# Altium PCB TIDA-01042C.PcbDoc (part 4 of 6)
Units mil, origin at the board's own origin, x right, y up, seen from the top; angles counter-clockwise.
Board outline 8300 x 7100 mil, 8 copper layers (Top Layer, Signal Layer 1, Signal Layer 2, Signal Layer 3, Signal Layer 4, Signal Layer 5, Signal Layer 6, Bottom Layer), stack 59.2 mil thick; 551 components, 303 nets, 1611 pads, 2322 vias.
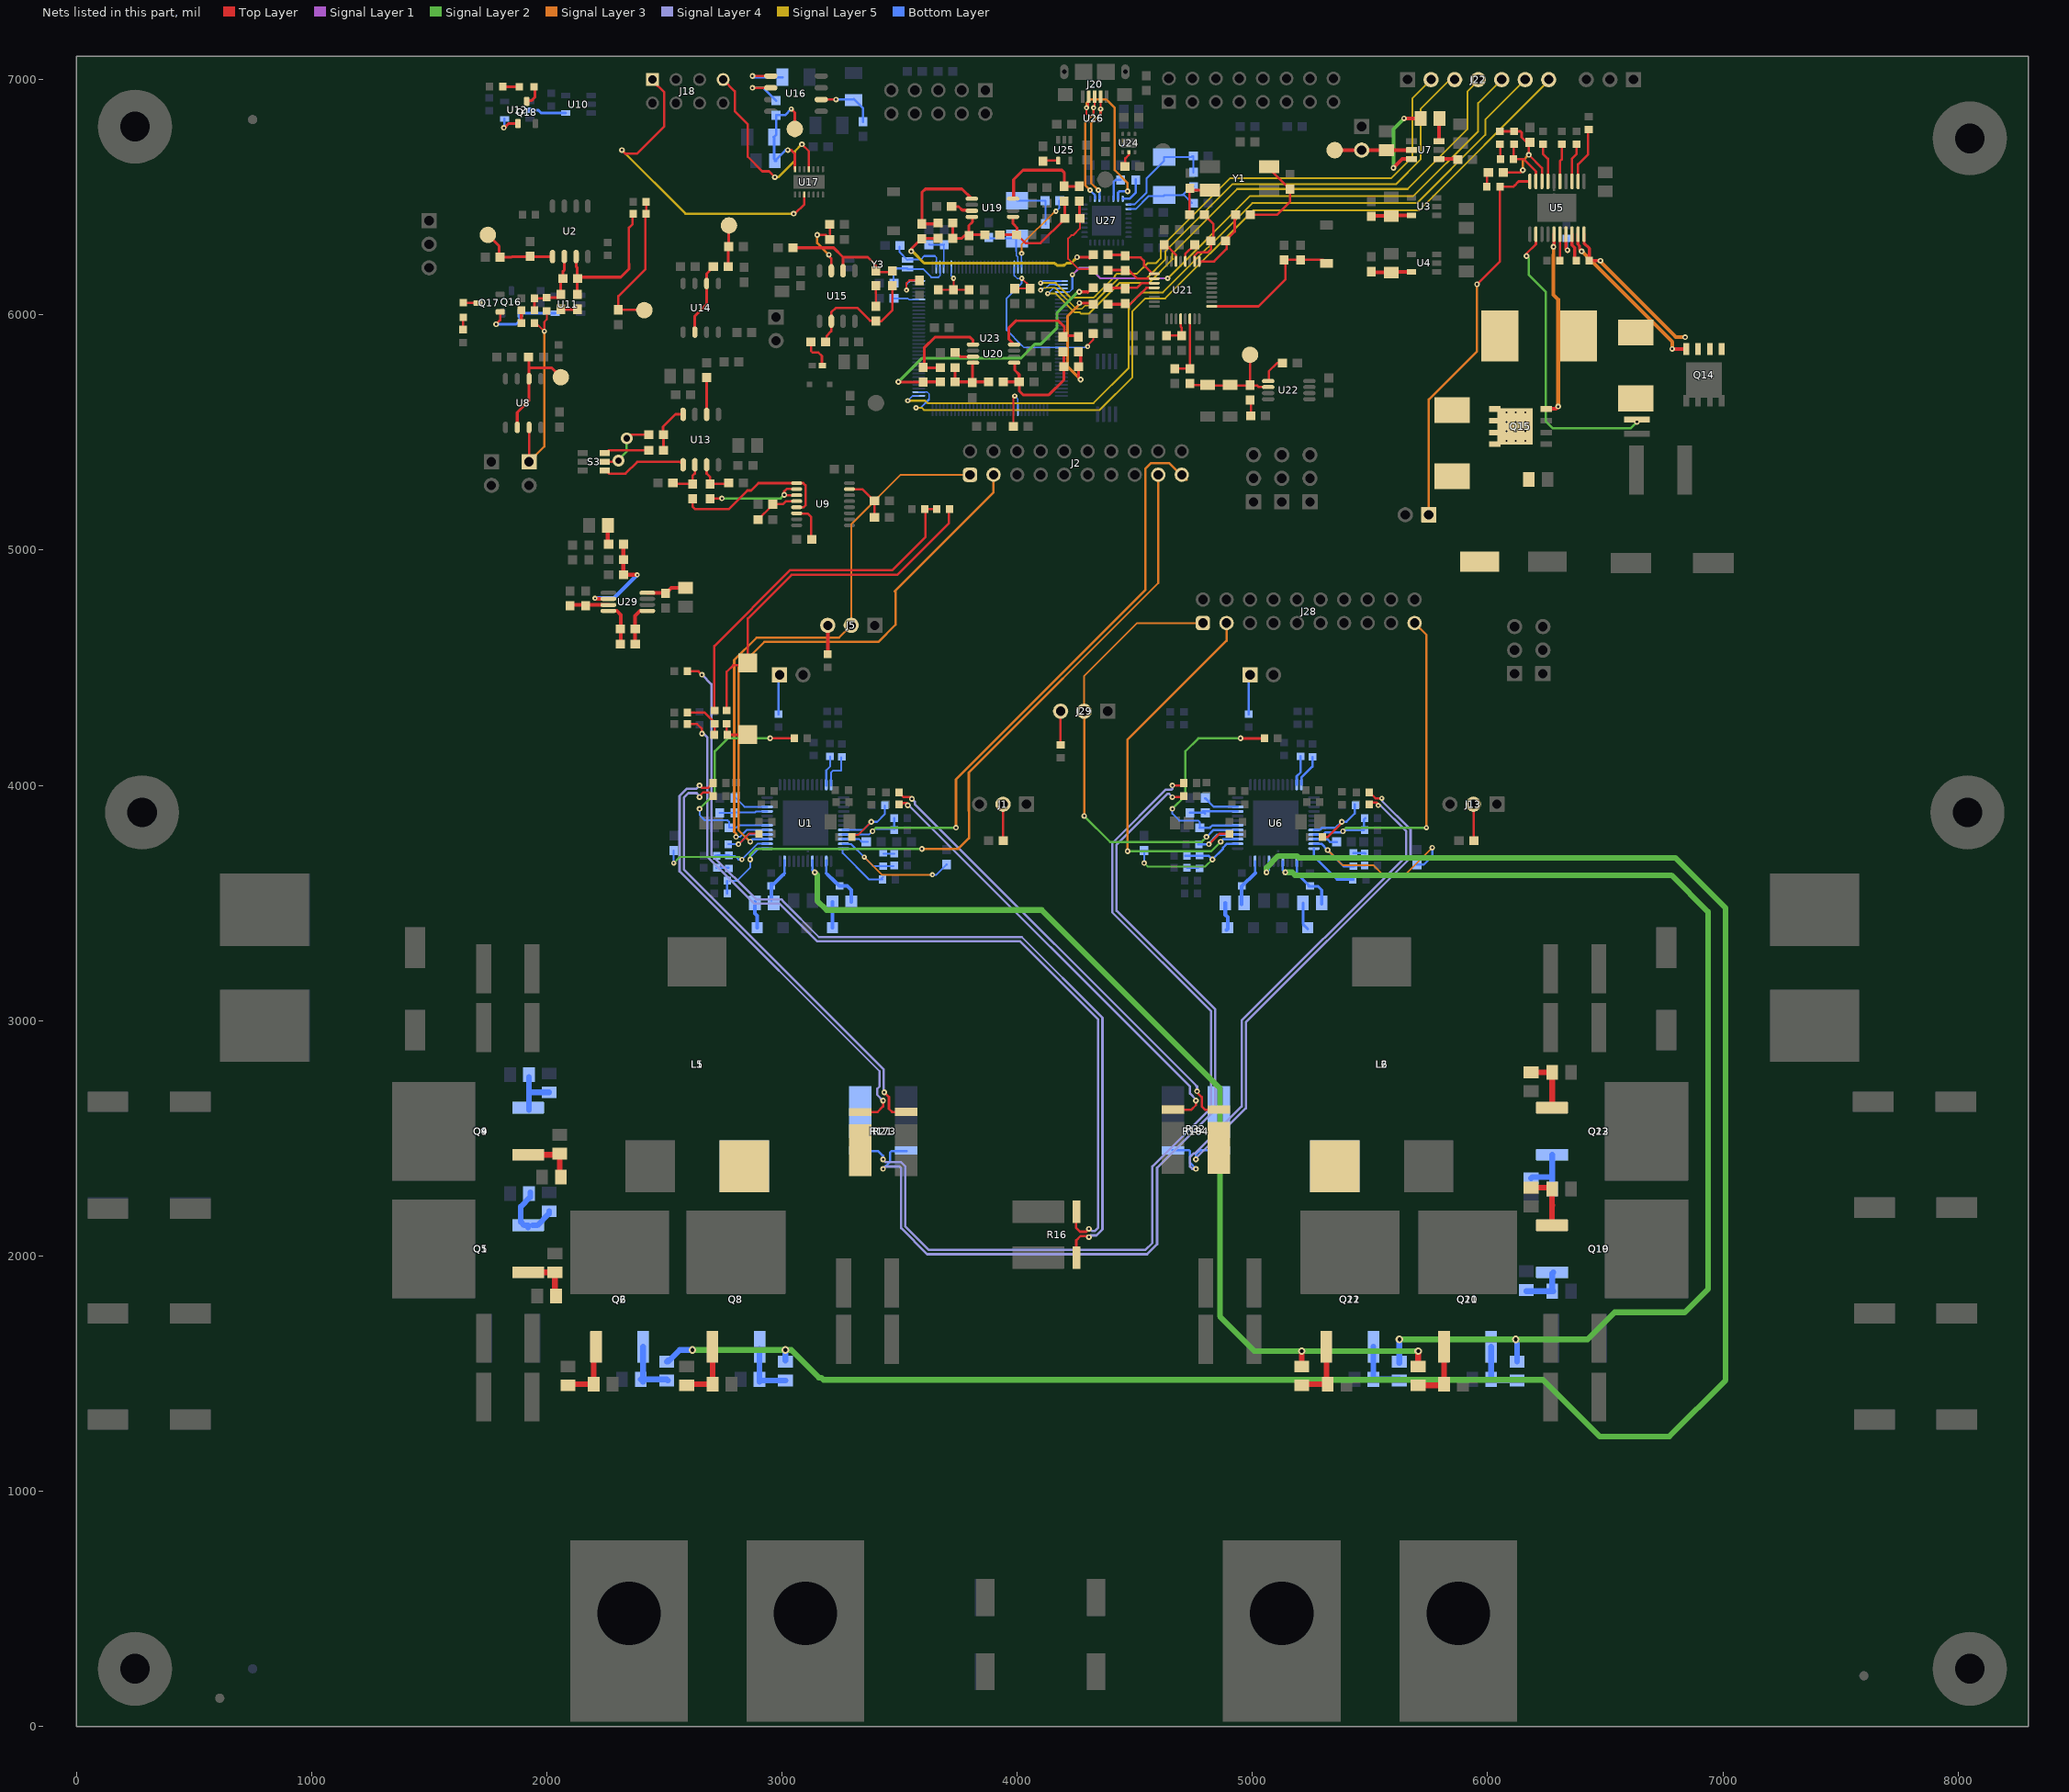
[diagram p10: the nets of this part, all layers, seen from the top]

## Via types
v1: diameter 32, hole 16, Top Layer to Bottom Layer, tented both sides, 1077 vias
v2: diameter 22, hole 8, Top Layer to Bottom Layer, tented both sides, 583 vias
v3: diameter 32, hole 16, Top Layer to Bottom Layer, 233 vias
v4: diameter 24, hole 10, Top Layer to Bottom Layer, tented both sides, 153 vias
v5: diameter 24, hole 8, Top Layer to Bottom Layer, 96 vias
v6: diameter 19.68, hole 7.87, Top Layer to Bottom Layer, 70 vias
v7: diameter 24, hole 10, Top Layer to Bottom Layer, 44 vias
v8: diameter 28, hole 8, Top Layer to Bottom Layer, tented top, 24 vias
v9: diameter 22, hole 8, Top Layer to Bottom Layer, 18 vias
v10: diameter 19.68, hole 8, Top Layer to Bottom Layer, 16 vias
v11: diameter 50, hole 28, Top Layer to Bottom Layer, 3 vias
v12: diameter 36, hole 20, Top Layer to Bottom Layer, 2 vias
v13: diameter 26, hole 12, Top Layer to Bottom Layer, 1 vias
v14: diameter 28, hole 12, Top Layer to Bottom Layer, tented both sides, 1 vias
v15: diameter 24, hole 10, Top Layer to Bottom Layer, tented top, 1 vias

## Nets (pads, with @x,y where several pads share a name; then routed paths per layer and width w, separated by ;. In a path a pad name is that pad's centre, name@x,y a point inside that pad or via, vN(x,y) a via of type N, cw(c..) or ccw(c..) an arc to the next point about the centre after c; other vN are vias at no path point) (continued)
LO2: R38.1 R39.1 U1.17 | length 4223.8
  Top Layer w24: R39.1@5210,1530 v1(5210,1595) ; R38.1@5705,1530 v1(5705,1595)
  Signal Layer 2 w24: v4@3141.87,3628.13 3150,3620 3150,3510 3190,3470 4105,3470 4861.87,2713.13 4861.87,1743.13 5010,1595 v1(5210,1595) v1(5705,1595)
  Bottom Layer w9.8: 3129.53,3640.47 U1.17@3129.53,3681.54
  Bottom Layer w12: 3129.53,3640.47 v4(3140,3630)
LO3: R180.1 R181.1 U6.20 | length 8995.4
  Signal Layer 2 w24: v1(2620,1600) v1(3015,1600) 3040,1600 3157.54,1482.46 3167.46,1482.46 3176.8,1473.13 6235.92,1473.13 ; v4(5060,3630) 5060,3650 5110,3700 5190.08,3700 5198.2,3691.87 6798.2,3691.87 6800.08,3690 6800.15,3690 7011.87,3478.28 7011.87,1471.8 6772.33,1232.25 6476.8,1232.25 6235.92,1473.13 ; 6254.52,1454.52 6235.92,1473.13
  Bottom Layer w9.8: v4(5060,3630) 5070.47,3640.47 U6.20@5070.47,3677.6
  Bottom Layer w24: R180.1@2515,1555 R180.1@2510,1550 2515,1550 2565,1600 v1(2620,1600) ; R181.1@3015,1555 v1(3015,1600)
LO4: R191.1 R192.1 U6.17 | length 5117.7
  Signal Layer 2 w24: v4(5140,3630) 5169.92,3630 5181.8,3618.13 6781.87,3618.13 6936.84,3463.16 6936.84,1858.63 6838.2,1760 6540,1760 6425,1645 v1(6120,1645) v1(5625,1645)
  Bottom Layer w9.8: U6.17@5129.53,3677.6 5129.53,3640.47 v4(5140,3630)
  Bottom Layer w24: R192.1@5625,1545 R192.1@5625,1550 v1(5625,1645) ; R191.1@6125,1550 v1@6125,1645
NetC1_1: C1.1 R1.2 U1.28 | length 287
  Top Layer w8: v4(2815,3750) 2860,3795 C1.1@2897.44,3795
  Bottom Layer w8: R1.2@2772.56,3750 v4(2815,3750) 2855.79,3790.79 U1.28@2941.54,3790.79
NetC3_2: C3.2 C4.2 R161.1 U1.26 | length 608.8
  Signal Layer 2 w8: v2(2540,3670) 2565,3695 2820,3695 v2(2830,3685)
  Bottom Layer w8: v2(2540,3670) R161.1@2540,3723.5 ; C4.2@2775,3700 2800,3700 2815,3685 v2(2830,3685) 2896.42,3751.42 U1.26@2941.54,3751.42
  Bottom Layer w9.8: C3.2@2716.9,3700 C3.2@2717.56,3700 ; C3.2@2725.12,3702.56 C4.2@2775,3702.56
NetC4_1: C4.1 R2.1 | length 49.9
  Bottom Layer w9.8: R2.1@2722.56,3650 C4.1@2772.44,3650
NetC5_1: C5.1 R5.2 U1.8 | length 348.7
  Top Layer w8: C5.1@3302.56,3780 3312.56,3790 3325,3790 v4(3380,3845)
  Bottom Layer w8: U1.8@3258.46,3810.47 3345.47,3810.47 v4(3380,3845) 3405,3845 3437.56,3877.56 R5.2@3437.56,3915
NetC7_2: C7.2 R54.1 U1.23 | length 188.2
  Bottom Layer w9.8: 3011.42,3626.42 U1.23@3011.42,3681.54
  Bottom Layer w12: 3005,3620 3011.42,3626.42
  Bottom Layer w16: R54.1@2955,3515 C7.2@2955,3572.44 ; C7.2@2955,3580 2965,3580 3005,3620
NetC8_1: C8.1 R8.2 U6.28 | length 296.1
  Top Layer w10: v4(4815,3750) 4860,3795 C8.1@4902.44,3795 C8.1@4905,3795
  Bottom Layer w9.8: R8.2@4770,3750 R8.2@4772.56,3750 v4(4815,3750) 4815,3755 4850.79,3790.79 U6.28@4937.6,3790.79
NetC12_1: C12.1 R55.1 U1.14 | length 242.9
  Bottom Layer w9.8: 3188.58,3626.42 U1.14@3188.58,3681.54
  Bottom Layer w12: 3188.58,3626.42 3195,3620 ; 3220,3595 3221.15,3595 3222.44,3595
  Bottom Layer w16: 3195,3620 3221.15,3595 C12.1@3245,3572.44 3277.56,3572.44 3295,3555 R55.1@3295,3505
NetC14_1: C14.1 U1.12 | length 241.7
  Bottom Layer w8: U1.12@3258.46,3731.73 3258.46,3711.54 3370,3600 C14.1@3427.44,3600 ; C14.1@3424.44,3605 C14.1@3428.94,3609.5
NetC15_1: C15.1 C16.1 R160.1 U1.11 | length 654.4
  Signal Layer 3 w8: v2(3350,3695) 3425,3620 v2(3640,3620)
  Bottom Layer w8: U1.11@3258.46,3751.42 3259.88,3750 3295,3750 v2(3350,3695) 3387.56,3657.44 C15.1@3430,3657.44 C16.1@3474.88,3657.44 ; v2(3640,3620) 3656.5,3620 R160.1@3700,3663.5
NetC15_2: C15.2 R19.2 | length 44.9
  Bottom Layer w8: C15.2@3432.56,3710 R19.2@3477.44,3710
NetC19_2: C19.2 C30.2 R44.1 U6.26 | length 621.3
  Signal Layer 2 w8: v4(4540,3670) 4555,3655 4800,3655 v4(4830,3685)
  Bottom Layer w8: v4(4540,3670) R44.1@4540,3723.5
  Bottom Layer w10: C19.2@4715,3700 C19.2@4722.56,3700 4815,3700 v4(4830,3685) 4875.85,3730.85 4875.85,3735.68 4891.59,3751.42 U6.26@4937.6,3751.42
NetC30_1: C30.1 R23.1 | length 47.4
  Bottom Layer w10: R23.1@4722.56,3650 C30.1@4770,3650
NetC31_1: C31.1 R43.2 U6.8 | length 353.7
  Top Layer w9.8: C31.1@5297.56,3780 5320,3780 5380,3840 v4(5380,3845)
  Bottom Layer w9.8: U6.8@5262.4,3810.47 5263.41,3811.48 5288.84,3811.48 5297.36,3820 5355,3820 v4(5380,3845) 5400,3845 5435,3880 R43.2@5435,3920
NetC35_1: C35.1 R164.1 U3.5 | length 171.9
  Top Layer w16: R164.1@5505,6420 C35.1@5590,6420 5592.6,6422.6 U3.5@5675.87,6422.6
NetC37_1: C37.1 R165.1 U4.5 | length 176.9
  Top Layer w16: R165.1@5505,6180 C37.1@5585,6180 ; C37.1@5590,6180 C37.1@5585,6180 ; U4.5@5675.87,6182.6 5587.6,6182.6 C37.1@5585,6180
NetC41_1: C41.1 D7.1 L3.1 Q14.1 Q14.2 Q14.3 U5.20 | length 674.1
  Top Layer w13: U5.20@6410.16,6342.8 6410.16,6304.84 6432.56,6282.44 C41.1@6432.56,6230 v4(6480,6230) v4@6485,6230
  Signal Layer 3 w13: v4@6480,6225 v4@6485,6230
  Signal Layer 3 w16: v4@6480,6225 6800,5905 v7(6840,5905)
NetC41_2: C41.2 U5.18 | length 120.4
  Top Layer w13: U5.18@6358.98,6342.8 6358.98,6296.02 6370,6285 6370,6237.44 C41.2@6377.44,6230
NetC42_1: C42.1 C43.1 D6.1 J4.1 R51.2 U5.10 | length 1656.9
  Top Layer w10: v4(5955,6130) 6052.56,6227.56 R51.2@6052.56,6545 6110,6545 6115.13,6550.13 6115.13,6550.3 6129.7,6564.87 6129.87,6564.87 6132.2,6567.2 U5.10@6179.84,6567.2
  Signal Layer 3 w10: J4.1@5750,5150 5750,5640 5955,5845 v4(5955,6130)
NetC44_1: C44.1 U5.7 | length 166.3
  Top Layer w10: C44.1@6235.31,6724.64 6235.31,6684.69 6256.61,6663.39 U5.7@6256.61,6567.2
NetC45_1: C45.1 U5.5 | length 160.6
  Top Layer w10: U5.5@6307.8,6567.2 6307.8,6652.8 6315.31,6660.31 C45.1@6315.31,6724.64
NetC46_1: C46.1 C49.1 U5.9 | length 219.5
  Top Layer w10: C49.1@6110.08,6722.2 C46.1@6110.08,6662.2 6152.8,6662.2 6205.43,6609.57 U5.9@6205.43,6567.2
NetC46_2: C46.2 R48.2 | length 63.5
  Top Layer w10: R48.2@6052.52,6724.64 6054.96,6722.2 C46.2@6054.96,6662.2
NetC47_1: C47.1 U5.17 | length 123
  Top Layer w13: U5.17@6333.39,6342.8 6333.39,6276.61 v4@6340,6270
  Bottom Layer w13: v4@6335,6280 C47.1@6335,6324.44 C47.1@6335,6327.44
  other v4: 6340,6275
NetC48_1: C48.1 U5.16 | length 114.2
  Top Layer w10: C48.1@6305,6227.44 C48.1@6307.56,6230 ; C48.1@6307.8,6232.2 U5.16@6307.8,6342.8
NetC49_2: C49.2 R48.1 R49.2 R50.1 U5.8 | length 530.5
  Top Layer w10: R48.1@6050,6780 6140,6780 6145,6775 6145,6755 6166.5,6733.5 R49.2@6178.5,6733.5 ; R50.1@6052.56,6605 6140,6605 v4(6150,6615) ; v4(6175,6680) 6175,6730 R49.2@6178.5,6733.5 ; v4@6175.31,6679.69 6231.02,6623.98 U5.8@6231.02,6567.2 ; R49.2@6180,6733.5 R49.2@6178.5,6733.5 ; R49.2@6180,6735 R49.2@6178.5,6733.5
  Signal Layer 3 w10: v4(6150,6615) 6150,6655 v4(6175,6680)
NetC77_1: C77.1 U7.6 | length 98.4
  Top Layer w16: U7.6@5793.07,6737.4 5793.07,6833.07 C77.1@5795,6835
NetC77_2: C77.2 U7.3 | length 391.1
  Top Layer w16: v7(5600,6625) 5637.6,6662.6 U7.3@5676.93,6662.6 ; v7(5645,6835) C77.2@5715,6835
  Signal Layer 2 w16: v7(5600,6625) 5600,6790 v7(5645,6835)
NetC78_1: C78.1 J16.2 U7.2 V-5.1 | length 330
  Top Layer w16: V-5.1@5350,6700 J16.2@5465,6700 U7.2@5676.93,6700 U7.2@5680,6700
NetC79_1: C79.1 CS2.1 R62.2 | length 1541.6
  Top Layer w10: C79.1@2765,4315 C79.1@2767.56,4317.56 ; C79.1@2765,4320 2765,4482.56 2792.44,4510 2840,4510 CS2.1@2850,4520 ; CS2.1@2855,4520 2855,4709.44 3040.56,4895 3490,4895 3710,5115 R62.2@3710,5177.44
NetC79_2: C79.2 CS1.1 R61.2 | length 137.4
  Top Layer w10: C79.2@2765,4262.44 2765,4215 R61.2@2767.56,4215 CS1.1@2855,4215
NetC85_1: C85.1 R62.1 R64.2 | length 1539.9
  Top Layer w10: C85.1@2710,4315 2712.44,4317.44 2712.44,4592.16 3035.28,4915 3470,4915 3610,5055 R64.2@3610,5175 ; R64.2@3607.56,5175 R64.2@3610,5175 ; R62.1@3660,5175 R62.1@3657.44,5175 R64.2@3610,5175
NetC85_2: C85.2 R61.1 R63.2 | length 185.6
  Top Layer w10: R63.2@2597.56,4310 2670,4310 C85.2@2715,4265 ; R61.1@2710,4215 2715,4220 C85.2@2715,4262.44
NetC87_1: C87.1 R76.2 R78.2 R80.2 R101.2 U2.6 | length 335.8
  Top Layer w12: R78.2@1945,6070 1947.56,6067.44 R101.2@1947.56,6020 ; R78.2@1947.56,6070 1995,6070 R76.2@2000,6075 ; R76.2@2000,6072.56 2042.56,6072.56 R80.2@2060,6090 ; R80.2@2060,6086.5 R80.2@2060,6090 ; C87.1@2068.5,6155 2068.5,6183.5 2075,6190 U2.6@2075,6247.72 ; C87.1@2070,6150 2060,6140 R80.2@2060,6090
NetC87_2: C87.2 C89.2 R81.2 U2.7 | length 634
  Top Layer w10: 2350,6216.69 2350,6370 2365,6385 R81.2@2365,6430
  Top Layer w12: U2.7@2125,6247.72 2125,6205 2130,6200 2130,6160 2315,6160 2350,6195 2350,6216.69 ; C89.2@2130,6086.5 C87.2@2130,6155
NetC89_1: C89.1 R80.1 | length 70.6
  Top Layer w12: R80.1@2060,6023.5 2128.5,6023.5 C89.1@2130,6025
NetC90_1: C90.1 R84.1 U2.5 VREF_LV.1 | length 339.9
  Top Layer w12: VREF_LV.1@1750,6340 1797.56,6292.44 1797.56,6245 R84.1@1801.5,6245 1850,6245 ; 1852.28,6247.72 U2.5@2025,6247.72
NetC100_1: C100.1 R65.1 U9.15 | length 197.2
  Top Layer w10: U9.15@3287.2,5258.98 3341.02,5258.98 3390,5210 R65.1@3393.5,5210 ; C100.1@3393.5,5140 3393.5,5208.5 R65.1@3395,5210
NetC102_1: C102.1 J35.1 R76.1 U8.3 | length 872.2
  Top Layer w8: C102.1@1945,5965 C102.1@1947.56,5965 1955,5965 v2(1990,5930) 1990,5970 2000,5980 R76.1@2000,6015
  Top Layer w10: J35.1@1925,5380 U8.3@1925,5521.65
  Signal Layer 3 w8: 1990,5440 v2(1990,5930)
  Signal Layer 3 w10: J35.1@1925,5375 1990,5440
NetC102_2: C102.2 R101.1 | length 52.4
  Top Layer w12: C102.2@1892.44,5965 R101.1@1892.44,6017.44
NetC104_1: C104.1 R68.1 U13.2 | length 174.1
  Top Layer w10: C104.1@2535,5285 2538.5,5281.5 R68.1@2620,5281.5 2620,5315 2630,5325 U13.2@2630,5362.72 U13.2@2630,5365
NetC105_1: C105.1 R69.1 U13.3 | length 171.2
  Top Layer w10: U13.3@2680,5365 U13.3@2680,5362.72 2680,5325 2695,5310 R69.1@2695,5281.5 2771.5,5281.5 C105.1@2775,5285
NetC114_1: C114.1 R74.2 R82.1 U15.2 | length 546.6
  Top Layer w10: 3260,6245 3365,6245 3400,6210 R82.1@3400,6190 ; R82.1@3400,6186.5 R82.1@3400,6190 ; C114.1@3480,6181.5 3408.5,6181.5 R82.1@3400,6190
  Top Layer w12: R74.2@3046.5,6285 3220,6285 3260,6245 U15.2@3260,6190
NetC114_2: C114.2 C115.1 R162.1 U15.6 | length 546.3
  Top Layer w10: R162.1@3190,5881.5 3190,5910 3210,5930 U15.6@3210,5972.72 3210,6010 3230,6030 3320,6030 3375,5975 C115.1@3400,5975 ; C115.1@3400,5973.5 3423.5,5973.5 3470,6020 3470,6105 C114.2@3480,6115
NetC115_2: C115.2 R82.2 | length 88.5
  Top Layer w10: C115.2@3400,6036.5 R82.2@3400,6123.5 R82.2@3400,6125
NetC118_2: C118.2 R93.2 U15.3 | length 304.4
  Top Layer w10: v4(3150,6340) 3185,6340 R93.2@3203.5,6321.5 ; v7@3200,6250 3210,6240 U15.3@3210,6187.28 ; C118.2@3203.5,6385 R93.2@3203.5,6321.5 ; R93.2@3205,6320 R93.2@3203.5,6321.5
  Signal Layer 3 w10: v4@3150,6345 v4(3150,6340) 3150,6305 v7(3200,6255)
NetC122_1: C122.1 L4.2 U16.2 | length 252.2
  Top Layer w10: U16.2@3167.28,6915 v7(3230,6915)
  Bottom Layer w10: v7(3230,6915) C122.1@3305,6915 ; C122.1@3305,6917.91 3345,6877.91 L4.2@3345,6821.5 L4.2@3345,6820
NetC123_1: C123.1 U16.5 | length 207.7
  Top Layer w10: v4(2875,7015) U16.5@2952.72,7015
  Bottom Layer w10: v4(2875,7015) 2880,7010 C123.1@3002.91,7010
NetC124_1: C124.1 C125.1 R96.2 U17.7 VREF_DAC.1 | length 543
  Top Layer w10: v4(3025,6700) 3040,6700 3055,6685 U17.7@3055,6620 ; v2(3040,6875) 3055,6860 VREF_DAC.1@3055,6790
  Bottom Layer w10: C125.1@2965,6755 2975,6765 R96.2@2975,6848.5 3013.5,6848.5 v2(3040,6875) ; C125.1@2967.09,6755 2967.09,6662.91 C124.1@2972.5,6657.5 ; C124.1@2970,6655 C124.1@2972.5,6657.5 ; C124.1@2975,6655 C124.1@2972.5,6657.5 ; v4(3025,6700) 3015,6700 C124.1@2972.5,6657.5
NetC142_1: C142.1 C143.1 R111.1 R112.2 U19.1 | length 494.7
  Top Layer w10: R112.2@4000,6340 4035,6305 4100,6305 4200,6405 R111.1@4200,6410
  Top Layer w12: C143.1@3926.5,6340 R112.2@3998.5,6340 4000,6340 4000,6370 3982.6,6387.4 U19.1@3982.6,6416.61 ; C142.1@4200,6485 4203.5,6481.5 R111.1@4203.5,6410
NetC142_2: C142.2 R113.1 U19.4 | length 439.8
  Top Layer w12: U19.4@3985,6495 3985,6575 4025,6615 4190,6615 4200,6605 C142.2@4200,6546.5 4263.5,6546.5 R113.1@4265,6545
NetC143_2: C143.2 C144.1 R114.2 R117.1 U19.8 | length 292.1
  Top Layer w12: C144.1@3725,6390 3726.5,6388.5 R117.1@3726.5,6325 3765,6325 3776.5,6336.5 R114.2@3795,6336.5 R114.2@3795,6340 ; U19.8@3810,6415 3810,6395 3795,6380 R114.2@3795,6340 ; C143.2@3863.5,6340 R114.2@3795,6340
NetC144_2: C144.2 R115.1 U19.5 | length 437.3
  Top Layer w12: R115.1@3595,6386.5 3661.5,6386.5 C144.2@3665,6390 ; R115.1@3595,6390 3595,6520 3610,6535 3765.79,6535 U19.5@3807.4,6493.39
NetC145_2: C145.2 C146.2 U21.12 | length 141.2
  Top Layer w10: C145.2@4635,5911.5 4698.5,5911.5 C146.2@4700,5910 ; U21.12@4695,5985 4695,5950 4700,5945 C146.2@4700,5911.5
NetC147_1: C147.1 R118.2 U21.1 | length 238.4
  Top Layer w10: C147.1@4460,6250 4466.13,6243.87 4524.89,6243.87 4538.87,6229.89 4538.87,6210.11 ; 4540,6215 4540,6210 4576.1,6173.9 U21.1@4582.95,6173.9
  Top Layer w12: R118.2@4386.5,6255 C147.1@4455,6255
NetC147_2: C147.2 R119.2 U21.2 | length 212.4
  Top Layer w10: C147.2@4476.5,6188.5 4510,6155 U21.2@4585,6155
  Top Layer w12: R119.2@4386.5,6190 C147.2@4460,6190 ; C147.2@4460,6188.5 C147.2@4476.5,6188.5
NetC148_1: C148.1 R125.2 U21.3 | length 206.6
  Top Layer w10: C148.1@4460,6115 4510,6115 4529.53,6134.53 U21.3@4582.95,6134.53
  Top Layer w12: R125.2@4386.5,6115 4455,6115 C148.1@4460,6110
NetC148_2: C148.2 R127.2 U21.4 | length 232.5
  Top Layer w10: C148.2@4460,6045 4480,6045 4550,6115 U21.4@4580.91,6115 ; U21.4@4580.91,6114.84 U21.4@4582.95,6114.84 ; U21.4@4582.95,6115 U21.4@4590,6115
  Top Layer w12: R127.2@4386.5,6045 C148.2@4460,6045
NetC149_2: C149.2 R121.1 S1.1 U21.17 | length 632.2
  Top Layer w10: U21.17@4827.05,6036.1 5026.1,6036.1 5140,6150 R121.1@5140,6230 ; R121.1@5135,6233.5 5201.5,6233.5 C149.2@5205,6230 ; C149.2@5200,6233.5 C149.2@5205,6233.5 5301.5,6233.5 S1.1@5315,6220
NetC150_1: C150.1 C151.1 R124.1 R126.2 U20.1 | length 544.3
  Top Layer w12: C151.1@3940,5715 C151.1@3941.5,5715 R126.2@4008.5,5715 4008.5,5746.5 3990,5765 U20.1@3990,5795 ; R126.2@4010,5715 4010,5675 4025,5660 4135,5660 4198.5,5723.5 R124.1@4198.5,5780 4198.5,5848.5 C150.1@4200,5850
NetC150_2: C150.2 R128.1 U20.4 | length 448.7
  Top Layer w10: 3995,5975 4175,5975
  Top Layer w12: U20.4@3987.6,5873.39 3965,5895.98 3965,5945 3995,5975 ; 4175,5975 4200,5950 4200,5911.5 4266.5,5911.5 R128.1@4270,5915
NetC151_2: C151.2 C154.1 R129.2 R132.1 U20.8 | length 297.7
  Top Layer w12: C154.1@3735,5780 3736.5,5778.5 C154.1@3736.5,5775 R132.1@3736.5,5715 R129.2@3810,5715 ; R129.2@3810,5711.5 R129.2@3810,5715 ; U20.8@3815,5799.47 3810,5794.47 R129.2@3810,5715 ; C151.2@3878.5,5715 R129.2@3810,5715
NetC152_1: C152.1 R135.2 Y1.1 | length 388
  Top Layer w10: R135.2@4991.5,6436.5 R135.2@4991.5,6425 5105,6425 5160,6480 C152.1@5160,6533.5 5075,6618.5 Y1.1@5075,6630
NetC153_1: C153.1 R136.1 Y1.3 | length 201.7
  Top Layer w10: R136.1@4733.5,6425 4733.5,6538.5 C153.1@4735,6540 ; C153.1@4735,6535 4740,6530 Y1.3@4819.02,6530
NetC154_2: C154.2 R130.1 U20.5 | length 403.9
  Top Layer w12: C154.2@3673.5,5775 3605,5775 3605,5860 3650,5905 3800,5905 3812.4,5892.6 U20.5@3812.4,5873.39
NetC155_1: C155.1 R133.2 U21.14 | length 280
  Top Layer w10: C155.1@4670,5775 4673.5,5771.5 R133.2@4735,5771.5 U21.14@4735,5985
NetC156_1: C156.1 U21.28 | length 90.1
  Top Layer w10: U21.28@4715,6225 4715,6258.5 C156.1@4755,6298.5
NetC157_1: C157.1 U22.5 | length 118
  Top Layer w10: U22.5@5070,5715 5070,5760 5105,5795 C157.1@5128.5,5795
NetC158_1: C158.1 C159.1 R133.1 R134.2 U22.6 VREF_ADC.1 | length 430.2
  Top Layer w10: R133.1@4735,5705 4738.07,5701.93 C159.1@4810,5701.93 ; C159.1@4810,5700 5020,5700 5027.2,5692.8 U22.6@5067.4,5692.8 ; R134.2@4990,5701.5 4990,5795
NetC161_1: C161.1 R134.1 | length 71.5
  Top Layer w10: R134.1@4990,5640 4993.5,5636.5 C161.1@4993.5,5570
NetC162_1: C162.1 U23.88 Y2.2 | length 241.9
  Bottom Layer w6: 3995,6270 3997.13,6267.87 3997.13,6251.94 4003.11,6245.96 U23.88@4003.11,6203.15
  Bottom Layer w8: C162.1@3880,6330 3885.71,6324.29 3995,6324.29 3995,6270
NetC163_2: C163.2 R146.2 U23.68 | length 161.7
  Bottom Layer w6: U23.68@3688.15,6203.15 3688.15,6298.15 3688.5,6298.5 R146.2@3690,6300
  Bottom Layer w8: C163.2@3625,6300 3626.5,6298.5 R146.2@3688.5,6298.5
NetC164_1: C164.1 R145.1 Y2.1 | length 217
  Bottom Layer w8: Y2.1@4000,6485 R145.1@4118.5,6485 ; C164.1@4120,6386.5 R145.1@4120,6485
NetC169_2: C169.2 R139.1 R141.2 U23.70 | length 237.9
  Top Layer w8: C169.2@3665,6106.5 R141.2@3795,6106.5 3803.5,6116.5 R141.2@3805,6115 ; R139.1@3730,6116.5 v2(3730,6155)
  Bottom Layer w6: U23.70@3720,6205 3720,6165 v2(3730,6155)
NetC170_2: C170.2 U23.67 Y3.1 | length 311
  Bottom Layer w6: 3665,6160 3672.4,6167.4 U23.67@3672.4,6203.15
  Bottom Layer w8: C170.2@3475,6135 3475,6190 3482.28,6197.28 Y3.1@3534.02,6197.28 Y3.1@3534.02,6194.02 ; Y3.1@3535,6195 3600,6195 3635,6160 3665,6160
NetC171_2: C171.2 U23.66 Y3.4 | length 237.2
  Bottom Layer w6: 3650,6250 3656.65,6243.35 U23.66@3656.65,6203.15
  Bottom Layer w8: C171.2@3500,6290 3500,6266.73 Y3.4@3534.02,6232.72 ; Y3.4@3540,6235 3590,6235 3605,6250 3650,6250
NetC172_1: C172.1 C173.1 C174.2 U23.87 U23.115 | length 904.8
  Top Layer w8: C172.1@3990,6125 C172.1@3990,6111.5 4053.5,6111.5 C173.1@4055,6110 ; v2(4020,6155) 4055,6120 C173.1@4055,6111.5 ; v2(4300,5865) 4300,5870 4323.5,5893.5 C174.2@4323.5,5920
  Bottom Layer w6: U23.87@3987.36,6203.15 3987.36,6167.64 4000,6155 v2(4020,6155) ; 4020,5870 4029.37,5860.63 U23.115@4188.15,5860.63 4295.63,5860.63 v2(4300,5865)
  Bottom Layer w8: 4020,5870 3955,5935 3955,6070 4020,6135 v2(4020,6155) ; v2@4295,5865 v2(4300,5865)
NetC181_1: C181.1 U24.2 | length 67.8
  Top Layer w10: C181.1@4460,6630 4460,6665 4475,6680 U24.2@4475,6691.61
NetC184_1: C184.1 U25.4 | length 64.7
  Top Layer w10: C184.1@4110,6655 4110.71,6655.71 U25.4@4174.41,6655.71
NetC185_2: C185.2 R150.2 U27.26 Y4.2 | length 382.2
  Bottom Layer w8: U27.26@4473.31,6449.21 4504.21,6449.21 4560,6505 Y4.2@4625,6505 ; Y4.2@4625,6509.29 4709.21,6509.29 ; 4700,6510 4703.5,6510 4709.21,6509.29 ; C185.2@4743.5,6475 4709.21,6509.29 ; R150.2@4750,6545 4740,6545 4704.29,6509.29 4709.21,6509.29
NetC186_2: C186.2 R150.1 U27.25 Y4.1 | length 471.3
  Bottom Layer w8: U27.25@4473.31,6468.9 4498.9,6468.9 4550,6520 4550,6580 4625,6655 Y4.1@4625,6670 ; Y4.1@4625,6670.71 4740.71,6670.71 C186.2@4745,6675 ; C186.2@4748.5,6675 4748.5,6606.5 R150.1@4750,6605
NetC192_2: C192.2 R95.1 U6.23 | length 205.3
  Bottom Layer w9.8: 5011.42,3651.43 U6.23@5011.42,3677.6 ; 5012.51,3627.51 5012.51,3650.34
  Bottom Layer w16: R95.1@4955,3495 4955,3570 5012.51,3627.51
NetC195_1: C195.1 R166.1 U6.14 | length 250.1
  Bottom Layer w9.8: 5188.58,3626.42 U6.14@5188.58,3677.6
  Bottom Layer w12: 5188.58,3626.42 5240,3575 5240,3570 5280,3570 5285,3565 5295,3555 R166.1@5295,3495
NetC197_1: C197.1 U6.12 | length 242.2
  Bottom Layer w10: U6.12@5262.4,3731.73 5262.4,3697.6 5360,3600 C197.1@5430,3600
NetC201_1: C201.1 C204.1 R168.1 U6.11 | length 908.4
  Signal Layer 3 w8: v4(5320,3725) 5385,3660 5515,3660 5555,3620 5640,3620 5650,3620 v4(5765,3735)
  Bottom Layer w10: U6.11@5262.4,3751.42 5293.58,3751.42 v4(5320,3725) 5390,3655 5430,3655 5435,3660 C204.1@5477.44,3660 ; R168.1@5699.93,3663.5 5728.5,3663.5 5765,3700 v4(5765,3735)
NetC201_2: C201.2 R172.2 | length 51.1
  Bottom Layer w10: C201.2@5430,3712.56 5477.44,3712.56 R172.2@5480,3710
NetC218_1: C218.1 R195.1 U9.4 | length 189.4
  Top Layer w10: C218.1@2898.5,5130 2958.5,5190 R195.1@2960,5190 ; R195.1@2965,5195 3005,5195 3017.8,5207.8 U9.4@3062.8,5207.8
NetC221_1: C221.1 C222.1 U29.1 | length 186.6
  Top Layer w15: C222.1@2375,4595 2375,4720 2396.61,4741.61 U29.1@2427.68,4741.61
NetC221_2: C221.2 C222.2 U29.8 | length 189.6
  Top Layer w15: U29.8@2262.32,4741.61 2298.39,4741.61 2315,4725 C222.2@2315,4595
NetC223_1: C223.1 L7.1 U29.4 | length 186.3
  Top Layer w15: U29.4@2427.68,4818.39 2508.39,4818.39 2530,4840 L7.1@2605,4840
NetC224_1: C224.1 C225.1 U29.7 | length 158.5
  Top Layer w15: C225.1@2105,4770 2107.8,4767.2 U29.7@2262.32,4767.2
NetC226_1: C226.1 C227.1 R201.1 U29.6 | length 459.6
  Top Layer w17: v2@2210,4795 2212.2,4792.8 U29.6@2262.32,4792.8 ; R201.1@2330,5025 2326.5,5021.5 C227.1@2326.5,4960 C226.1@2326.5,4895 v2@2380,4895
  Bottom Layer w17: v2(2205,4795) 2285,4795 v2(2385,4895)
NetCV_1: CV.1 R81.1 R86.1 R163.1 | length 618.3
  Top Layer w10: R163.1@2305,6021.5 2413.5,6021.5 CV.1@2415,6020 ; R163.1@2305,6025 2305,6080 2420,6195 R81.1@2420,6430 ; R81.1@2422.56,6430 R86.1@2422.56,6485
NetD1_1: D1.1 R54.2 | length 114.1
  Bottom Layer w16: R54.2@2885,3505 2885,3455 2894.88,3445.12 D1.1@2894.88,3395
NetD2_1: D2.1 R55.2 | length 109.9
  Bottom Layer w16: D2.1@3215.12,3395 R55.2@3215.12,3504.88
NetD3_1: D3.1 R162.2 | length 133.9
  Top Layer w10: R162.2@3123.5,5885 3123.5,5846.5 3130,5840 3155,5840 3170,5825 D3.1@3170,5785
NetD4_1: D4.1 R95.2 | length 121.2
  Bottom Layer w16: R95.2@4885,3500 4885,3450 4895,3440 4895,3390 D4.1@4890,3385
NetD6_2: D6.2 L3.2 Q15.5 Q15.6 Q15.7 Q15.8 Q15.9
  other v8: 6080,5465 6120,5465 6160,5465 6080,5505 6120,5505 6160,5505 6080,5545 6120,5545 6160,5545 6080,5585 6120,5585 6160,5585
NetD7_2: D7.2 R47.2 U5.12 | length 1257.4
  Top Layer w10: v4(6165.53,6250) 6165.53,6260.53 6205.43,6300.43 U5.12@6205.43,6342.8
  Signal Layer 2 w10: v4(6165.53,6250) 6175,6240.53 6175,6170 6247.13,6097.87 6247.13,5547.87 6277.87,5517.13 6607.13,5517.13 v7(6635,5545)
NetD10_1: D10.1 R166.2 | length 118.3
  Bottom Layer w12: R166.2@5215,3500 5215,3410 D10.1@5235,3390
NetD11_1: D11.1 Q17.3 | length 64.8
  Top Layer w10: D11.1@1645,6050 1702.76,6050 Q17.3@1707.76,6045
NetD11_2: D11.2 R90.2 | length 52.4
  Top Layer w10: R90.2@1645,5937.56 D11.2@1645,5988.5 D11.2@1645,5990
NetD12_1: D12.1 Q18.3 | length 92.4
  Top Layer w12: Q18.3@1915,6907.24 1917.76,6910 1935,6910 1950,6925 D12.1@1950,6975
NetD12_2: D12.2 R91.2 | length 68.5
  Top Layer w12: R91.2@1815,6970 D12.2@1883.5,6970
NetIBAT_1: IBAT.1 R72.2 R73.2 | length 181.2
  Top Layer w12: R72.2@2771.5,6205 2771.5,6288.5 2770,6290 R73.2@2773.5,6293.5 ; R73.2@2773.5,6290 R73.2@2773.5,6293.5 ; IBAT.1@2775,6380 2773.5,6378.5 R73.2@2773.5,6293.5
NetJ1_2: J1.2 R4.2 | length 152.6
  Top Layer w9.8: R4.2@3940,3767.44 J1.2@3940,3920
NetJ3_1: J3.1 R7.1 | length 167.4
  Bottom Layer w10: R7.1@2985,4302.56 J3.1@2985,4470
NetJ5_3: J5.3 R12.1 | length 130
  Top Layer w16: R12.1@3195,4555 J5.3@3195,4685
NetJ13_2: J13.2 R34.2 | length 155.6
  Top Layer w10: J13.2@5940,3920 5941.5,3918.5 R34.2@5941.5,3765
NetJ18_1: J18.1 U17.10 | length 1398.1
  Top Layer w10: v7(2320,6700) 2335,6685 2383.5,6685 2500,6801.5 2500,6945 J18.1@2450,6995 ; v7(3050,6430) 3055,6430 3095.31,6470.32 U17.10@3095.31,6510.87
  Signal Layer 5 w10: v7(2320,6700) 2590,6430 v7(3050,6430) v7@3055,6430
NetJ18_7: J18.7 U17.4 | length 837.5
  Top Layer w10: J18.7@2750,7000 2800,6950 2800,6865 2855,6810 2855,6671.5 2916.5,6610 2945,6610 v7(2970,6585) ; v4(3085,6725) 3115,6695 U17.4@3115,6619.13
  Signal Layer 5 w10: v7(2970,6585) 2985,6585 3055,6655 3055,6695 v4(3085,6725)
NetJ20_2: J20.2 U26.1 U27.19 | length 503.5
  Top Layer w8: U26.1@4345,6845 4355,6855 v2(4355,6875) 4355.59,6875.59 J20.2@4355.59,6927.6
  Signal Layer 3 w10: v2(4345,6530) 4315,6560 4315,6815 4355,6855 v2(4355,6875)
  Bottom Layer w10: v2@4342.5,6532.5 v2(4345,6530) 4350.47,6524.53 U27.19@4350.47,6493.31
NetJ20_3: J20.3 U26.2 U27.18 | length 495.7
  Top Layer w8: U26.2@4325,6845 v2(4325,6880) 4330,6885 J20.3@4330,6927.6
  Signal Layer 3 w10: v2(4310,6530) 4290,6550 4290,6820 4325,6855 v2(4325,6880)
  Bottom Layer w10: v2@4315,6525 4330.79,6509.21 U27.18@4330.79,6493.31
NetJ20_4: J20.4 U26.3 U27.23 | length 698.2
  Top Layer w8: J20.4@4304.41,6927.6 4302.13,6925.32 4302.13,6887.13 v2(4295,6880) 4295,6855 U26.3@4305,6845
  Signal Layer 3 w10: v2(4295,6880) 4295,6900 4310,6915 4380,6915 4415,6880 4415,6615 4470,6560 v4(4470,6525)
  Bottom Layer w10: U27.23@4429.21,6493.31 4429.21,6519.21 4435,6525 v4(4470,6525)
NetJ22_2: J22.2 U23.97 | length 2346.3
  Signal Layer 5 w8: v2(4100,6135) 4165,6135 4226.13,6073.87 4326.22,6073.87 ; 4333.78,6081.22 4326.42,6073.87 4326.22,6073.87 ; 4415,6165 4425,6175 4510,6175 4554.07,6219.07 ; 4416.17,6163.83 4326.22,6073.87 ; 4555,6220 4554.07,6219.07 ; J22.2@5760,7000 5680,6920 5680,6670 5590,6580 4905,6580 4610,6285 4610,6240 4589.07,6219.07 4554.07,6219.07
  Bottom Layer w6: v2(4100,6135) 4109.09,6144.09 U23.97@4188.15,6144.09
NetJ22_3: J22.3 U23.98 | length 2456.6
  Signal Layer 5 w6: v2(4100,6105) 4105,6105 4115,6115 4161.03,6115 4251.03,6025 4275,6025 ; 4280,6030 4275,6025 ; 4315,6040 4290,6040 4275,6025
  Signal Layer 5 w8: 4315,6040 4430,6155 4550,6155 4630,6235 4630,6270 4915,6555 5610,6555 5715,6660 5715,6875 5840,7000 J22.3@5860,7000
  Bottom Layer w6: v2(4100,6105) 4108.13,6113.13 4121.87,6113.13 4137.09,6128.35 U23.98@4188.15,6128.35
NetJ22_4: J22.4 U23.99 | length 2449.7
  Signal Layer 5 w8: v2(4130,6090) 4165,6090 4244.87,6010.13 4266.52,6010.13 4271.65,6005 4305,6005 4310,6010 4435,6135 4560,6135 4662.5,6237.5 ; 4660,6240 4660,6260 4935,6535 5660,6535 5915,6790 5915,6950 J22.4@5960,6995
  Bottom Layer w6: v2(4130,6090) 4152.6,6112.6 U23.99@4188.15,6112.6
NetJ22_5: J22.5 U23.100 | length 2388.7
  Signal Layer 1 w8: v2(4235,6170) 4265,6200 4310,6200 4355,6155 v2(4640,6155)
  Signal Layer 5 w8: v2(4640,6155) 4990,6505 5685,6505 5960,6780 5960,6900 J22.5@6060,7000
  Bottom Layer w6: U23.100@4188.15,6096.85 4221.85,6096.85 4235,6110
  Bottom Layer w8: 4235,6110 v2(4235,6170)
NetJ22_6: J22.6 U23.33 | length 3447.5
  Signal Layer 5 w8: v2(3535,5635) 3610,5635 3620,5625 4325,5625 4474.13,5774.13 4474.13,6021.58 4475,6022.45 4475,6040 4530,6095 4620,6095 5000,6475 5700,6475 5990,6765 5990,6830 J22.6@6160,7000
  Bottom Layer w6: v2(3535,5635) 3555.91,5655.91 U23.33@3581.85,5655.91
NetJ22_7: J22.7 U23.34 | length 3583.5
  Signal Layer 5 w8: v2(3570,5605) 3595,5605 3605,5595 4350,5595 4490,5735 4490,6015 4545,6070 4630,6070 5005,6445 5710,6445 6260,6995 J22.7@6260,7000
  Bottom Layer w6: U23.34@3581.85,5671.65 3618.35,5671.65 3625,5665 3625,5640
  Bottom Layer w8: v2(3570,5605) 3590,5605 3625,5640
NetJ27_1: J27.1 R89.1 | length 178.7
  Bottom Layer w10: R89.1@4985,4302.56 4985,4460 J27.1@5000,4475
NetJ29_3: J29.3 R157.1 | length 142.4
  Top Layer w10: R157.1@4185,4172.56 J29.3@4185,4315
NetL1_2: L1.2 R21.1
NetL2_1: L2.1 R32.2
NetL5_1: L5.1 R173.1
NetL6_2: L6.2 R184.2
NetL8_2: L8.2 R201.2 | length 81.5
  Top Layer w17: L8.2@2260,5105 2260,5028.5 R201.2@2263.5,5025
NetQ1_1: Q1.1 R22.2 R26.2 | length 232.2
  Top Layer w24: Q1.1@1915,1924.67 1920.33,1930 R22.2@2040,1930 ; R26.2@2035,1825 R22.2@2035,1930
NetQ2_1: Q2.1 R24.1 R27.2 | length 278.9
  Top Layer w24: R27.2@2080,1455 R24.1@2200,1455 2200,1525 Q2.1@2200,1613.94
NetQ3_1: Q3.1 R25.1 R28.2 | length 283.1
  Top Layer w24: R28.2@2590,1445 2600,1455 R25.1@2705,1455 2705,1525 Q3.1@2705,1613.94 Q3.1@2705,1618.94
NetQ4_1: Q4.1 R29.2 R30.2 | length 256.7
  Top Layer w24: Q4.1@1920.33,2430 R29.2@2055,2430 ; R30.2@2055,2320 R29.2@2055,2430 ; R29.2@2055,2435 R29.2@2055,2430 ; R29.2@2060,2425 R29.2@2055,2430
NetQ5_1: Q5.1 R174.2 R179.2 | length 289.6
  Bottom Layer w24: Q5.1@1921.06,2120 Q5.1@1921.06,2130 1905,2130 1890,2145 1890,2210 1930,2250 R179.2@1930,2270 ; Q5.1@1940,2130 1960,2130 2010,2180 R174.2@2010,2190
NetQ6_1: Q6.1 R175.1 R180.2 | length 277.2
  Bottom Layer w24: R175.1@2410,1465 R175.1@2405,1470 ; Q6.1@2410,1613.94 R175.1@2410,1475 ; R180.2@2515,1470 2510,1475 R175.1@2410,1475 ; R175.1@2405,1470 R175.1@2410,1475 ; R175.1@2405,1470 R175.1@2400,1475 R175.1@2410,1475
NetQ8_1: Q8.1 R176.1 R181.2 | length 243.9
  Bottom Layer w24: R176.1@2905,1465 Q8.1@2905,1603.94 ; R176.1@2910,1470 R181.2@3015,1470
NetQ9_1: Q9.1 R182.2 R183.2 | length 225
  Bottom Layer w24: Q9.1@1925,2620 1925,2695 ; R183.2@1925,2760 1925,2695 ; R182.2@2010,2695 1925,2695
NetQ10_1: Q10.1 R33.1 R37.2 | length 255.2
  Top Layer w24: R33.1@6180,2285 R33.1@6185,2290 6270,2290 6273.94,2286.06 6273.94,2213.94 ; Q10.1@6273.94,2130 6273.94,2213.94 ; 6275,2215 6273.94,2213.94
NetQ11_1: Q11.1 R35.1 R38.2 | length 276
  Top Layer w24: R38.2@5705,1450 5810,1450 R35.1@5815,1445 ; R35.1@5815,1455 Q11.1@5815,1613.94 Q11.1@5815,1618.94
NetQ12_1: Q12.1 R36.1 R39.2 | length 281
  Top Layer w24: R39.2@5205,1450 5210,1455 R36.1@5315,1455 ; R36.1@5315,1450 R36.1@5315,1455 ; Q12.1@5315,1613.94 5315,1525 R36.1@5315,1455 ; R36.1@5320,1455 R36.1@5315,1455
NetQ13_1: Q13.1 R40.1 R41.2 | length 245
  Top Layer w24: R40.1@6185,2780 R41.2@6275,2780 ; Q13.1@6275,2630 R41.2@6275,2780 ; R41.2@6280,2780 R41.2@6275,2780
NetQ14_4: Q14.4 U5.19 | length 718.2
  Top Layer w13: U5.19@6384.57,6342.8 6384.57,6299.95 6390.87,6293.65 6390.87,6279.13 v4(6400,6270) v4@6400,6274.76
  Top Layer w16: v7(6785,5855) 6785.7,5854.3 Q14.4@6844.51,5854.3
  Signal Layer 3 w16: v4(6400,6270) 6785,5885 v7(6785,5855)
NetQ15_4: Q15.4 U5.15 | length 797
  Top Layer w13: v4@6282.2,6292.2 U5.15@6282.2,6342.8
  Top Layer w14: v4@6280,6290 v4@6282.2,6292.2
  Top Layer w16: Q15.4@6249.3,5600.49 6290.49,5600.49 v7(6300,5610)
  Signal Layer 3 w14: 6280,6255 6280,6258.37 6280.5,6258.87 6280.5,6289.5 v4@6280,6290
  Signal Layer 3 w16: 6280,6255 6280,6085 6300,6065 v7(6300,5610)
  other v4: 6280,6289
NetQ16_1: Q16.1 Q17.1 U11.4 | length 339.2
  Top Layer w10: v4(1785,5960) 1802.24,5977.24 Q17.1@1802.24,6007.6
  Bottom Layer w10: v4(1785,5960) 1870,5960 1885,5975 Q16.1@1885,6010
  Bottom Layer w12: Q16.1@1892.6,6007.6 U11.4@2035.87,6007.6
NetQ18_1: Q18.1 U12.4 | length 102.9
  Top Layer w12: v4@1820,6795 1837.76,6812.76 Q18.1@1877.6,6812.76
  Bottom Layer w10: v4@1820,6795 1820.87,6795.87 U12.4@1820.87,6832.6
  other v4: 1817.6,6795
NetQ19_1: Q19.1 R185.1 R190.2 | length 197.1
  Bottom Layer w24: R185.1@6165,1850 R190.2@6275,1850 ; R190.2@6280,1850 R190.2@6275,1850 ; Q19.1@6280,1930 6275,1925 R190.2@6275,1850
NetQ20_1: Q20.1 R188.1 R191.2 | length 251
  Bottom Layer w24: R188.1@6010,1475 6015,1480 Q20.1@6015,1613.94 ; R188.1@6015,1470 R191.2@6125,1470
NetQ21_1: Q21.1 R189.1 R192.2 | length 251
  Bottom Layer w24: R189.1@5515,1475 R189.1@5520,1475 ; Q21.1@5515,1613.94 5515,1480 R189.1@5520,1475 ; R192.2@5625,1475 R189.1@5520,1475
NetQ22_1: Q22.1 R193.1 R194.2 | length 237.1
  Bottom Layer w24: R193.1@6185,2330 6190,2335 6275,2335 ; R194.2@6275,2285 6275,2335 ; Q22.1@6275,2430 6275,2335
NetR10_2: R10.2 U7.4 | length 83
  Top Layer w16: U7.4@5793.07,6662.6 5872.4,6662.6 R10.2@5875,6660
NetR11_2: R11.2 U1.48 | length 158
  Bottom Layer w8: U1.48@3208.27,3998.46 3208.27,4053.27 3218.33,4063.33 3252.44,4063.33 3252.44,4065 R11.2@3252.44,4118.21
NetR13_2: R13.2 U1.47 | length 130.8
  Bottom Layer w8: U1.47@3188.58,3998.46 3188.58,4063.58 3205,4080 R13.2@3205,4122.44
NetR15_2: R15.2 R102.1 U1.30 | length 1014
  Top Layer w9.8: v7(2950,4200) R102.1@3052.44,4200
  Signal Layer 2 w9.8: v7@2645,3895 v7(2650,3900) 2715,3965 ; 2715,3960 2715,3965 ; v7(2950,4200) 2770,4200 2715,4145 2715,3965
  Bottom Layer w8: v7(2650,3900) 2650,3873.89 2671.94,3851.94 2768.06,3851.94 2775,3845 R15.2@2775,3820 ; R15.2@2776.5,3820 R15.2@2776.5,3833.5 ; R15.2@2777.56,3820 2805,3820 2815.16,3830.16 U1.30@2941.54,3830.16
NetR16_1: R16.1 R31.2 | length 3658.7
  Top Layer w9.8: R31.2@2597.56,4260 2640,4260 2660,4240 v4(2660,4220) ; R16.1@4255,2155 R16.1@4255,2175
  Top Layer w10: R16.1@4251.3,2187.64 4251.3,2118.7 4267.13,2102.87 4292.7,2102.87 4294.7,2104.87 4294.87,2104.87 v4@4300,2110
  Signal Layer 4 w9.8: v4(2660,4220) v4@2667.33,4220 ; 2990.01,3497.33 3150.18,3337.15
  Signal Layer 4 w10: v4@2667.33,4220 2682.33,4205 2682.33,3697.67 2882.67,3497.33 2990.01,3497.33 ; 3150.18,3337.15 4012.85,3337.15 4325,3025 4345,3005 4345,2120 4330,2105 4320,2105 4310,2115 v4(4305,2115)
NetR16_2: R16.2 R42.2 | length 3911
  Top Layer w9.8: R42.2@2595,4485 R42.2@2597.56,4485 2645,4485 v7(2660,4470)
  Top Layer w10: R16.2@4251.5,1992.36 4251.5,2066.5 4270,2085 4300,2085 v4(4305,2080)
  Signal Layer 4 w9.8: v7(2660,4470) 2700.2,4429.8
  Signal Layer 4 w10: 2700.2,4429.8 2700.2,3705.08 2890.08,3515.2 2997.41,3515.2 3007.88,3504.73 3007.88,3504.59 3157.44,3355.03 4020.25,3355.03 4362.87,3012.4 4362.87,2112.6 4337.4,2087.13 4312.13,2087.13 v4(4305,2080)
NetR21_3: R21.3 R56.2 | length 1967.7
  Top Layer w10: v4(2650,4000) 2660,3990 2687.44,3990 R56.2@2707.44,4010 ; R21.3@3332.36,2611.3 3406.3,2611.3 3430,2635 v4(3430,2660)
  Signal Layer 4 w9.8: 3415,2720.04 3415,2785
  Signal Layer 4 w10: v4(2650,4000) 2635,3985 2609.92,3985 2609.72,3985.2 2594.92,3985.2 2565,3955.28 2565,3635 3415,2785 ; 3415,2720.04 3405.23,2710.26 3405.23,2684.77 v4(3430,2660)
NetR21_4: R21.4 R57.2 | length 1912.4
  Top Layer w10: v4@2650,3955 2665,3970 2692.44,3970 R57.2@2707.44,3955 ; v4(3435,2695) 3455,2675 3455,2625 3468.5,2611.5 R21.4@3527.64,2611.5
  Signal Layer 4 w9.8: v4(2650,3950) 2650,3955 v4@2650,3958.27
  Signal Layer 4 w10: v4@2650,3955 2637.87,3967.13 2602.52,3967.13 2602.32,3967.33 2582.87,3947.88 2582.87,3642.4 3432.87,2792.4 3432.87,2777.6 3432.77,2777.5 3432.77,2727.54 3432.87,2727.44 3432.87,2712.63 3432.67,2712.43 v4@3432.67,2702.67
NetR32_3: R32.3 R59.2 | length 1946.3
  Top Layer w9.8: v7@3530,3920 v7(3535,3915) ; v4(4760,2660) v4@4760,2665
  Top Layer w10: R59.2@3497.56,3920 3510,3920 3515,3925 v7@3530,3925 ; R32.3@4662.36,2621.3 4740.77,2621.3 4760,2640.53 v4(4760,2660)
  Signal Layer 4 w9.8: v7@3530,3920 v7(3535,3915) ; v4(4760,2660) v4@4760,2664.96
  Signal Layer 4 w10: v7(3535,3915) 3543.87,3915 3543.87,3911.25 4735.23,2719.89 4735.23,2689.74 v4@4760,2664.96
NetR32_4: R32.4 R58.2 | length 1962.5
  Top Layer w10: R58.2@3497.56,3970 3517.56,3950 3545,3950 v4@3550,3945 ; v4(3552.57,3942.43) 3552.57,3942.57 v4@3555,3945 ; v4(4765,2700) 4765,2695 4785,2675 4785,2635 4798.5,2621.5 R32.4@4857.64,2621.5
  Signal Layer 4 w10: v4(3552.57,3942.43) 3565,3930 3565,3920 4760,2725 4765,2720 v4(4765,2700)
NetR45_1: R45.1 U6.10 | length 102.2
  Bottom Layer w9.8: U6.10@5262.4,3771.1 5318.9,3771.1 5330,3760 R45.1@5358.5,3760 R45.1@5360,3760
NetR46_2: R46.2 U5.3 | length 165.4
  Top Layer w10: U5.3@6358.98,6567.2 6358.98,6663.98 6378.11,6683.11 R46.2@6378.11,6724.64
NetR50_2: R50.2 R51.1 | length 60
  Top Layer w10: R51.1@5997.44,6545 R50.2@5997.44,6605
NetR52_2: R52.2 U8.2 U8.6 VBAT.1 | length 475.9
  Top Layer w12: U8.2@1875,5520 U8.2@1875,5521.65 1875,5585 1925,5635 U8.6@1925,5728.35 1925,5775 ; R52.2@1923.5,5820 1923.5,5821.5 1925,5820 1925,5775 ; VBAT.1@2060,5735 2020,5775 1925,5775
NetR53_2: R53.2 U5.2 | length 233
  Top Layer w10: U5.2@6384.57,6567.2 6384.57,6639.57 6427.44,6682.44 6427.44,6740 R53.2@6427.44,6782.44
NetR60_1: R60.1 U1.10 | length 111.1
  Bottom Layer w8: U1.10@3258.46,3771.1 3328.9,3771.1 3340,3760 3362.44,3760 R60.1@3365,3760
NetR67_2: R67.2 U9.6 | length 168.9
  Top Layer w10: U9.6@3058.5,5156.5 3060,5155 3110,5155 3125,5140 3125,5046.5 R67.2@3126.5,5045
NetR68_2: R68.2 U9.1 U9.5 | length 698.9
  Top Layer w10: R68.2@2620,5225 R68.2@2620,5218.5 2620,5185 2630,5175 2775,5175 2853.43,5253.43 2869.06,5253.43 2900.2,5284.57 U9.1@3062.8,5284.57 3090.43,5284.57 3100,5275 3100,5190 3092.2,5182.2 U9.5@3062.8,5182.2
NetR69_2: R69.2 U9.2 U9.3 | length 448.8
  Top Layer w10: R69.2@2695,5220 v4(2745,5220) ; U9.3@3062.8,5233.39 3011.61,5233.39 v4(3010,5235) 3010,5250 3020,5260 U9.2@3065,5260
  Signal Layer 2 w10: v4(2745,5220) 2995,5220 v4(3010,5235)
NetR70_1: R70.1 R200.1 U13.8 | length 192.3
  Top Layer w12: R200.1@2495,5430 2496.5,5431.5 R70.1@2496.5,5490 ; R70.1@2495,5500 2495,5525 2547.28,5577.28 U13.8@2580,5577.28
NetR70_2: R70.2 S3.2 | length 254
  Top Layer w10: S3.2@2247.24,5375 v11@2295,5375 ; v11@2350,5480 2360,5490 R70.2@2433.5,5490
  Signal Layer 2 w10: v11@2295,5375 2340,5420 v11(2340,5475)
  other v11: 2305,5380
NetR71_2: R71.2 U13.6 | length 152.7
  Top Layer w12: U13.6@2680,5577.28 R71.2@2680,5730
NetR72_1: R72.1 U14.2 U14.6 | length 308.1
  Top Layer w12: U14.2@2630,5926.65 2630,5995 2680,6045 U14.6@2680,6130 ; U14.6@2680,6133.35 2680,6175 R72.1@2710,6205
NetR92_2: R92.2 R94.1 U6.33 | length 214.3
  Bottom Layer w9.8: R92.2@4735.07,3883.5 4796.5,3883.5 R94.1@4800,3880 ; R94.1@4790,3890 4790.79,3889.21 U6.33@4937.6,3889.21
NetR94_2: R94.2 U6.34 | length 152.6
  Bottom Layer w9.8: R94.2@4800,3945 4836.1,3908.9 U6.34@4937.6,3908.9
NetR96_1: R96.1 U16.6 | length 200.5
  Top Layer w10: v4(2875,6965) U16.6@2952.72,6965
  Bottom Layer w10: v4(2875,6965) 2920,6965 R96.1@2975,6910
NetR111_2: R111.2 R113.2 R119.1 | length 404.6
  Top Layer w8: R111.2@4265,6410 R111.2@4266.5,6410 4266.5,6366.5 4237.87,6337.87 4230.53,6337.87 4217.13,6324.47 4217.13,6237.87 4260,6195 4320,6195 R119.1@4325,6190
  Top Layer w12: R111.2@4265,6410 R113.2@4265,6483.5 ; R119.1@4325,6190 R119.1@4330,6190
NetR115_2: R115.2 R117.2 R118.1 | length 963.5
  Top Layer w12: v7(3550,6270) 3550,6280 3560,6290 3595,6325 R117.2@3663.5,6325 ; v7(4255,6245) 4303.5,6245 4308.5,6240 R118.1@4323.5,6255
  Signal Layer 5 w12: v7(3550,6270) 3555,6270 3560,6265 3605,6220 4159.82,6220 4164.95,6214.87 4169.7,6210.13 4175.05,6210.13 4175.42,6209.75 4182.13,6209.75 4196.03,6209.75 4197.03,6210.75 4200.93,6210.75 4210.18,6220 4230,6220 4250,6240 v7(4255,6245)
NetR116_1: R116.1 U19.7 | length 89.7
  Top Layer w12: R116.1@3721.5,6460 3752.02,6460 3766.95,6445.06 3804.94,6445.06 U19.7@3805,6445
NetR120_1: R120.1 U21.30 | length 89.7
  Top Layer w10: R120.1@4630,6295 4635,6295 4675.47,6254.53 U21.30@4675.47,6227.05
NetR124_2: R124.2 R127.1 R128.2 | length 560.2
  Top Layer w12: R124.2@4260,5780 4270,5790 R128.2@4270,5848.5 ; R124.2@4261.5,5780 4261.5,5733.5 v7(4270,5725) ; v4(4265,6050) 4318.5,6050 R127.1@4323.5,6045
  Signal Layer 3 w12: v4(4265,6050) 4265,6045 4215,5995 4215,5780 v7(4270,5725)
NetR125_1: R125.1 R130.2 R132.2 | length 1212.6
  Top Layer w12: v7@3496.5,5713.5 R130.2@3600,5713.5 ; R130.2@3600,5710 3605,5715 R132.2@3673.5,5715 ; v7(4264,6097.75) 4297.25,6097.75 4300,6095 R125.1@4320,6115 ; R125.1@4321.75,6113.25 R125.1@4323.5,6115
  Signal Layer 2 w12: v7(3495,5715) 3595,5815 4015,5815 4075,5875 4100,5875 4170,5945 4170,6010 4257.75,6097.75 v7(4264,6097.75)
NetR131_1: R131.1 U20.7 | length 86.8
  Top Layer w12: R131.1@3735,5845 3757.8,5822.2 U20.7@3812.4,5822.2
NetR135_1: R135.1 R137.2 U21.25 | length 301.1
  Top Layer w10: U21.25@4773.9,6227.05 4837.05,6227.05 4890,6280 4890,6310 R137.2@4885,6315 ; R137.2@4886.5,6315 4925,6353.5 R135.1@4925,6425
NetR136_2: R136.2 R137.1 U21.26 | length 273.5
  Top Layer w10: U21.26@4754.21,6227.05 4754.21,6251.64 4767.58,6265 4810,6265 4825,6280 R137.1@4825,6315 ; R136.2@4795,6425 4835,6385 4835,6326.5 R137.1@4823.5,6315
NetR140_1: R140.1 U23.64 | length 172.5
  Top Layer w8: v2(3530,6105) 3530,6135 3541.5,6146.5 R140.1@3585,6146.5
  Bottom Layer w6: 3540,6140 3544.09,6144.09 U23.64@3581.85,6144.09
  Bottom Layer w8: v2(3530,6105) 3530,6130 3540,6140
NetR142_2: R142.2 U23.9 | length 196.3
  Top Layer w8: R142.2@3983.5,5525 3983.5,5648.5 v2(3990,5655)
  Bottom Layer w6: v2(3990,5655) 4003.11,5641.89 U23.9@4003.11,5596.85
NetR143_1: R143.1 U23.59 | length 108.8
  Bottom Layer w6: 3535,6070 3539.65,6065.35 U23.59@3581.85,6065.35
  Bottom Layer w8: R143.1@3475,6070 R143.1@3476.5,6070 3535,6070
NetR144_1: R144.1 R167.2 U6.30 | length 984.7
  Top Layer w12: v4(4950,4200) R144.1@5052.44,4200 R144.1@5055,4200
  Signal Layer 2 w9.8: v4(4660,3900) 4715,3955 4715,4145 4770,4200 v4(4950,4200)
  Bottom Layer w8: 4660,3878.33 4660,3880 ; v4(4660,3900) 4660,3880 ; 4700,3850.57 4689.43,3850.57 ; R167.2@4776.5,3820 4776.5,3843.5 4769.43,3850.57 4689.43,3850.57 ; 4660,3880 4689.43,3850.57
  Bottom Layer w9.8: R167.2@4775,3820 R167.2@4776.5,3820 4820,3820 4830.16,3830.16 U6.30@4937.6,3830.16
NetR145_2: R145.2 U23.89 | length 350.9
  Signal Layer 3 w8: v2(4019,6261) 4019,6299 4160,6440 v2(4165,6440)
  Bottom Layer w6: U23.89@4018.86,6203.15 4018.86,6258.86 v2@4020,6260
  Bottom Layer w8: v2(4165,6440) 4180,6455 R145.2@4180,6485
NetR148_2: R148.2 U6.48 | length 137
  Bottom Layer w10: U6.48@5208.27,4002.4 5208.27,4033.27 5255,4080 R148.2@5255,4120
NetR149_1: R149.1 U27.22 | length 108.5
  Bottom Layer w10: U27.22@4410,6490 4410,6565 4418.5,6573.5 R149.1@4440,6573.5
NetR153_2: R153.2 U27.24 | length 122.2
  Bottom Layer w10: U27.24@4448.9,6493.31 4478.31,6493.31 4505,6520 R153.2@4505,6573.5 R153.2@4505,6575
NetR155_1: R155.1 R156.2 U1.33 | length 205
  Bottom Layer w8: R156.2@2735,3883.5 2798.5,3883.5 2800,3885 2885,3885 2889.21,3889.21 U1.33@2937.6,3889.21
NetR155_2: R155.2 U1.34 | length 154.6
  Bottom Layer w8: R155.2@2800,3950 2841.1,3908.9 U1.34@2937.6,3908.9
NetR158_2: R158.2 U6.47 | length 129.4
  Bottom Layer w10: U6.47@5188.58,4002.4 5188.58,4038.86 5205,4055.28 R158.2@5205,4122.44 R158.2@5205,4125
NetR173_3: R173.3 R177.2 | length 3976.7
  Top Layer w9.8: v4(4660,4000) 4700,4000 R177.2@4710,4010
  Signal Layer 4 w10: v4(3430,2410) 3442.13,2397.87 3467.13,2397.87 3507.13,2397.87 3525,2380 3525,2125 3625,2025 4545,2025 4575,2055 4575,2380.28 4824.8,2630.08 4824.8,3039.92 4404.8,3459.92 4404.8,3755.08 4630.87,3981.15 4656.15,3981.15 4660,3985 v4(4660,4000)
  Bottom Layer w10: R173.3@3340,2445 3410,2445 3430,2425 v4(3430,2410)
NetR173_4: R173.4 R178.2 | length 4022.4
  Top Layer w9.8: v15(4660,3950) 4705,3950 R178.2@4710,3955
  Signal Layer 4 w10: v4(3430,2370) 3440,2380 3455,2380 3499.72,2380 3507.13,2372.6 3507.13,2117.6 3617.6,2007.13 4552.4,2007.13 4595,2049.72 ; 4595,2070 4595,2049.72 ; 4645,3963.28 4638.27,3963.28 4422.67,3747.68 4422.67,3467.32 4842.67,3047.32 4842.67,2622.68 4595,2375.01 4595,2049.72 ; 4646.72,3963.28 v15(4660,3950)
  Bottom Layer w10: v4(3430,2370) 3460,2400 3460,2440 3465,2445 R173.4@3530,2445
NetR184_3: R184.3 R187.2 | length 2216.2
  Top Layer w10: R187.2@5497.56,3920 5505,3920 5512.13,3927.13 5527.87,3927.13 v2@5540,3915
  Signal Layer 4 w10: v4(4760,2370) 4745,2370 4735,2380 4735,2415.16 4735.13,2415.28 4735.13,2420.3 4749.7,2434.87 4754.59,2434.87 4954.8,2635.08 4954.8,3000.08 5654.8,3700.08 5654.8,3804.92 5544.72,3915 v2(5535,3915)
  Bottom Layer w10: R184.3@4660,2450 4730,2450 4735,2445 4735,2395 v4(4760,2370)
NetR184_4: R184.4 R186.2 | length 2163.7
  Top Layer w10: R186.2@5497.56,3970 5498.25,3970 5523.25,3945 v2(5550,3945)
  Signal Layer 4 w10: v4@4760,2415.01 4972.67,2627.68 4972.67,2992.68 5672.67,3692.68 5672.67,3807.33 ; v2@5552.57,3942.43 5552.57,3932.43 5672.87,3812.13 5672.87,3795
  Bottom Layer w10: v4(4760,2410) 4760,2430 4780,2450 R184.4@4865,2450
NetR200_2: R200.2 S3.3 | length 189.7
  Top Layer w10: S3.3@2250,5410 2265,5425 R200.2@2433.5,5425
NetS3_1: S3.1 U13.1 | length 362
  Top Layer w10: S3.1@2250,5340 2265,5325 2335,5325 2385,5375 2567.72,5375 U13.1@2580,5362.72
NetU10_4: U10.4 U12.2 | length 156.9
  Bottom Layer w12: U12.2@1929.13,6870 1965,6870 1977.4,6857.6 U10.4@2080.87,6857.6
NFAULT: J2.3 U1.27 | length 2385.2
  Signal Layer 3 w9.8: v4@2870,3760 2865,3760 2815,3810 2815,4500 2925,4610 3410,4610 3482.5,4682.5 3482.5,4827.5 ; 3480,4825 3482.5,4827.5 ; J2.3@3905,5300 3900,5295 3900,5245 3482.5,4827.5
  Bottom Layer w9.8: v4(2865.55,3760.55) 2876.1,3771.1 U1.27@2937.6,3771.1 U1.27@2941.54,3771.1
nFAULT2: J28.3 U6.27 | length 1983.5
  Signal Layer 2 w9.8: v4(4865.55,3760.55) 4825,3720 ; 4825,3720 v4(4470,3720) 4825,3720
  Signal Layer 3 w9.8: v4(4470,3720) 4470,4195 4890,4615 J28.3@4890,4685
  Bottom Layer w9.8: v4@4865,3760 v4(4865.55,3760.55) 4876.1,3771.1 U6.27@4937.6,3771.1
OPT: J2.1 J5.2 U1.29 | length 2511.8
  Signal Layer 3 w8: J5.2@3295,4680 3295,5110 3505,5320 3780,5320 J2.1@3800,5300
  Signal Layer 3 w10: v4(2805,3781) 2805,3794.86 2797.23,3802.64 2797.23,4532.23 2892.77,4627.77 3242.77,4627.77 J5.2@3295,4680 ; J2.1@3800,5300 J2.1@3800,5320
  Bottom Layer w8: v4(2805,3781) 2821,3781 2850,3810 ; 2850.47,3810.47 U1.29@2937.6,3810.47 U1.29@2941.54,3810.47
OPT2: J28.1 J29.2 U6.29 | length 1912.3
  Signal Layer 2 w9.8: v4(4285,3870) 4395,3760 4785,3760 v4@4805,3780
  Signal Layer 3 w8: J29.2@4285,4315 4285,4465 4510,4690 J28.1@4790,4690
  Signal Layer 3 w9.8: v4(4285,3870) J29.2@4285,4315
  Bottom Layer w9.8: v4@4805,3780 4835.47,3810.47 U6.29@4937.6,3810.47
  other v4: 4805,3781
OVPA: C82.1 J2.19 R17.2 U1.9 | length 2697.1
  Signal Layer 2 w10: v4@3390,3810 3400,3820 v4(3740,3820)
  Signal Layer 3 w10: v4(3740,3820) 3740,4025.28 4545,4830.28 4545,5345 4570,5370 4645,5370 J2.19@4700,5315 ; J2.19@4700,5300 J2.19@4720,5300
  Bottom Layer w8: U1.9@3258.46,3790.79 3370.79,3790.79 v4(3385,3805) 3394.49,3814.49 3477.44,3814.49 R17.2@3479.49,3814.49
  Bottom Layer w10: R17.2@3477.44,3814.49 C82.1@3477.44,3860
OVPA2: C202.1 J28.19 R169.2 U6.9 | length 1527.5
  Signal Layer 2 w10: v4(5385,3805) 5400,3820 v2(5740,3820)
  Signal Layer 3 w10: J28.19@5690,4690 5740,4640 v2(5740,3820)
  Bottom Layer w9.8: U6.9@5262.4,3790.79 5300.79,3790.79 5310,3800 5385,3800 v4(5385,3805) 5390,3810 5475,3810 5475,3855 C202.1@5480,3860
OVPB: C83.1 J2.17 R18.2 U1.25 | length 3157.3
  Signal Layer 2 w10: v4(2865,3685) 2865,3705 2890,3730 v4(3595,3730)
  Signal Layer 3 w10: v4(3595,3730) 3750,3730 3795,3775 3795,3890.51 3794.65,3890.86 3794.65,4054.65 4600,4860 J2.17@4600,5320
  Bottom Layer w8: R18.2@2777.56,3595 2810,3595 2865,3650 v4(2865,3685) 2865,3695 2901.73,3731.73 U1.25@2937.6,3731.73 U1.25@2941.54,3731.73
  Bottom Layer w10: C83.1@2767.56,3540 R18.2@2767.56,3592.56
